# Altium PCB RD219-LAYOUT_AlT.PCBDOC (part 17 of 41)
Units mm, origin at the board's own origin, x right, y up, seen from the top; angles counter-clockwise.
Board outline 209.75 x 159.97 mm, 2 copper layers (TOP, BOTTOM), stack 0 mm thick; 398 components, 199 nets, 1469 pads, 0 vias.
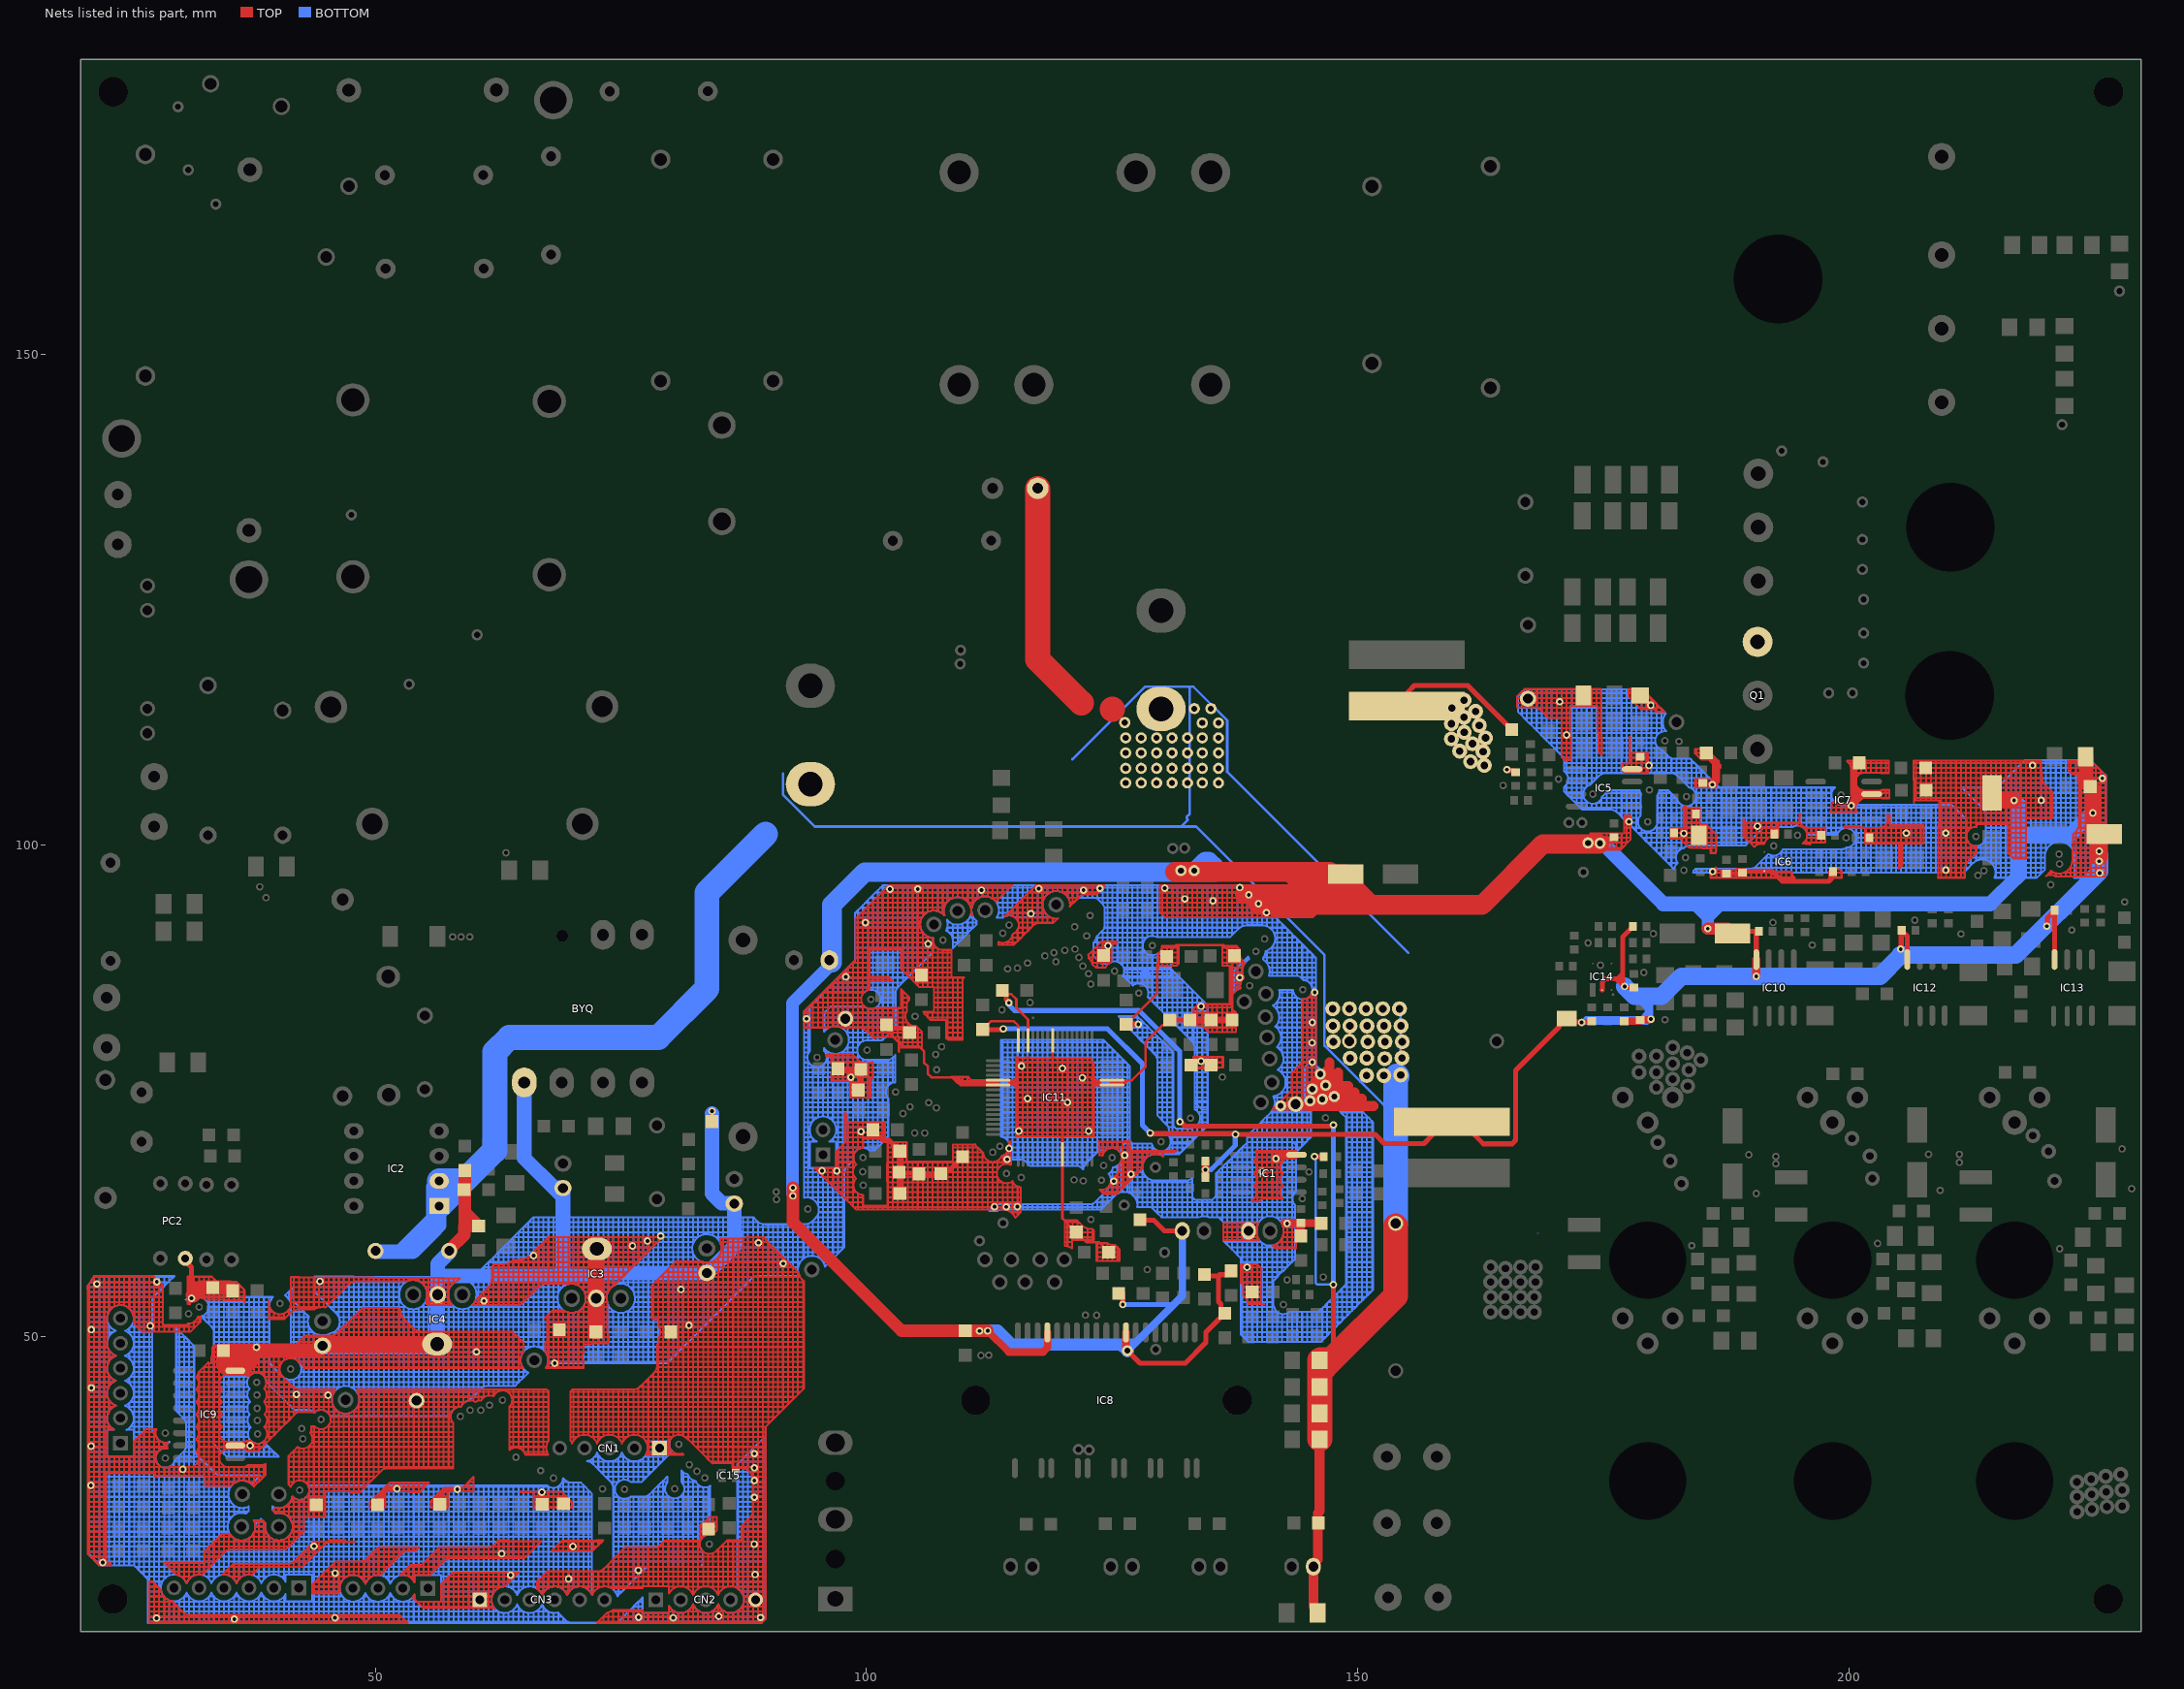
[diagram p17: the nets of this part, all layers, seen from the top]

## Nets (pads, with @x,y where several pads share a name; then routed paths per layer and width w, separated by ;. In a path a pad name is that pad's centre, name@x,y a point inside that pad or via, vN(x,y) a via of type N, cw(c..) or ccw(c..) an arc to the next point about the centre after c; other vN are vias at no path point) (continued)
GND: (continued)
  TOP w0.203: 201.737,101.775 202.245,101.775 ; 201.737,104.849 202.245,104.849 ; 201.737,104.849 201.737,105.217 IC7.3@201.737,105.344 ; IC7.3@201.737,105.344 IC7.3@202.245,105.344 ; IC7.3@201.737,105.344 201.737,105.585 ; 201.737,105.585 202.245,105.585 ; 201.737,107.389 202.245,107.389 ; 201.737,107.389 201.737,107.884 ; 201.737,107.884 202.245,107.884 ; 201.737,107.884 201.737,108.392 ; 201.737,108.392 202.245,108.392 ; 201.737,108.392 201.737,108.631 ; 201.737,108.631 202.245,108.631 ; 202.245,100.173 202.245,100.264 ; 202.245,100.264 202.753,100.264 ; 202.245,100.264 C17.1@202.245,100.772 ; C17.1@202.245,100.772 202.753,100.772 ; C17.1@202.245,100.772 202.245,101.28 ; 202.245,101.28 202.753,101.28 ; 202.245,101.28 202.245,101.775 ; 202.245,101.775 202.753,101.775 ; 202.245,104.849 202.753,104.849 ; 202.245,104.849 202.245,105.217 IC7.3@202.245,105.344 ; IC7.3@202.245,105.344 202.245,105.585 ; IC7.3@202.245,105.344 IC7.3@202.753,105.344 ; 202.245,105.585 202.753,105.585 ; 202.245,107.389 202.245,107.884 ; 202.245,107.389 202.753,107.389 ; 202.245,107.884 202.245,108.392 ; 202.245,107.884 202.753,107.884 ; 202.245,108.392 202.245,108.631 ; 202.245,108.392 202.753,108.392 ; 202.245,108.631 202.753,108.631 ; 202.753,100.172 202.753,100.264 ; 202.753,100.172 203.261,100.172 ; 202.753,100.264 202.753,100.772 ; 202.753,100.264 203.261,100.264 ; 202.753,100.772 203.261,100.772 ; 202.753,100.772 202.753,101.28 ; 202.753,101.28 203.261,101.28 ; 202.753,101.28 202.753,101.775 ; 202.753,101.775 203.051,101.775 ccw(c203.051,102.677) 203.201,101.788 ; 202.753,104.849 203.051,104.849 cw(c203.051,103.947) 203.201,104.836 ; 202.753,104.849 202.753,105.217 IC7.3@202.753,105.344 ; IC7.3@202.753,105.344 IC7.3@203.261,105.344 ; IC7.3@202.753,105.344 202.753,105.585 ; 202.753,105.585 203.051,105.585 ccw(c203.051,106.487) 203.261,105.61 ; 202.753,107.389 202.753,107.884 ; 202.753,107.389 203.051,107.389 cw(c203.051,106.487) 203.201,107.376 ; 202.753,107.884 203.261,107.884 ; 202.753,107.884 202.753,108.392 ; 202.753,108.392 203.261,108.392 ; 202.753,108.392 202.753,108.631 ; 202.753,108.631 203.261,108.631 ; 203.201,101.788 ccw(c203.051,102.677) 203.261,101.8 ; 203.201,101.788 203.261,101.788 ; 203.201,104.836 cw(c203.051,103.947) 203.261,104.824 ; 203.201,104.836 203.261,104.836 ; 203.201,107.376 cw(c203.051,106.487) 203.261,107.364 ; 203.201,107.376 203.261,107.376 ; 203.261,100.172 203.261,100.264 ; 203.261,100.172 203.769,100.172 ; 203.261,100.264 203.261,100.772 ; 203.261,100.264 203.769,100.264 ; 203.261,100.772 203.261,101.28 ; 203.261,100.772 203.769,100.772 ; 203.261,101.28 203.261,101.788 ; 203.261,101.28 203.769,101.28 ; 203.261,101.788 203.769,101.788 ; 203.261,101.788 203.261,101.8 ; 203.261,101.8 ccw(c203.051,102.677) 203.769,102.132 ; 203.261,104.824 203.261,104.836 ; 203.261,104.836 203.769,104.836 ; 203.261,104.836 IC7.3@203.261,105.344 ; IC7.3@203.261,105.344 203.769,105.344 ; IC7.3@203.261,105.344 203.261,105.61 ; 203.261,107.364 203.261,107.376 ; 203.261,107.376 203.769,107.376 ; 203.261,107.376 203.261,107.884 ; 203.261,107.884 203.769,107.884 ; 203.261,107.884 203.261,108.392 ; 203.261,108.392 203.769,108.392 ; 203.261,108.392 203.261,108.631 ; 203.261,108.631 203.769,108.631 ; 203.769,100.172 204.277,100.172 ; 203.769,100.172 203.769,100.264 ; 203.769,100.264 204.277,100.264 ; 203.769,100.264 203.769,100.772 ; 203.769,100.772 204.277,100.772 ; 203.769,100.772 203.769,101.28 ; 203.769,101.28 204.277,101.28 ; 203.769,101.28 203.769,101.788 ; 203.769,101.788 204.277,101.788 ; 203.769,101.788 203.769,102.132 ; 203.769,102.132 ccw(c203.051,102.677) 203.771,102.134 ccw(c203.051,102.677) 203.868,102.296 ; 203.769,104.799 203.769,104.836 ; 203.769,104.799 204.092,104.799 204.092,104.836 ; 203.769,104.836 203.769,105.344 ; 203.769,104.836 204.092,104.836 ; 203.769,105.344 203.769,105.635 ; 203.769,105.344 204.092,105.344 ; 203.769,105.635 204.092,105.635 204.092,105.344 ; 203.769,107.339 203.769,107.376 ; 203.769,107.339 204.041,107.339 204.041,107.376 ; 203.769,107.376 203.769,107.884 ; 203.769,107.376 204.041,107.376 ; 203.769,107.884 203.769,108.392 ; 203.769,107.884 204.041,107.884 ; 203.769,108.392 203.769,108.631 ; 203.769,108.392 204.041,108.392 ; 203.769,108.631 204.041,108.631 204.041,108.392 ; 203.85,103.095 cw(c203.051,102.677) 203.944,102.804 ; 203.85,103.095 204.168,103.095 204.168,102.804 ; 203.868,102.296 ccw(c203.051,102.677) 203.953,102.677 ccw(c203.051,102.677) 203.944,102.804 ; 203.868,102.296 204.168,102.296 ; 203.944,102.804 204.168,102.804 ; 204.041,107.376 204.041,107.884 ; 204.041,107.884 204.041,108.392 ; 204.092,104.836 204.092,105.344 ; 204.168,102.296 204.168,102.804 ; 204.168,102.296 204.168,102.06 204.277,102.06 ; 204.277,100.172 204.277,100.264 ; 204.277,100.172 204.785,100.172 ; 204.277,100.264 204.277,100.772 ; 204.277,100.264 204.785,100.264 ; 204.277,100.772 204.277,101.28 ; 204.277,100.772 204.785,100.772 ; 204.277,101.28 204.277,101.788 ; 204.277,101.28 204.785,101.28 ; 204.277,101.788 204.785,101.788 ; 204.277,101.788 204.277,102.06 ; 204.277,102.06 204.785,102.06 ; 204.785,100.172 204.785,100.264 ; 204.785,100.172 205.078,100.172 205.078,99.756 ; 204.785,100.264 204.785,100.772 ; 204.785,100.264 205.293,100.264 ; 204.785,100.772 204.785,101.28 ; 204.785,100.772 205.293,100.772 ; 204.785,101.28 204.785,101.788 ; 204.785,101.28 205.293,101.28 ; 204.785,101.788 204.785,102.06 ; 204.785,101.788 205.293,101.788 ; 204.785,102.06 205.293,102.06 ; 205.078,97.724 205.078,98.232 ; 205.078,97.724 205.078,97.646 205.431,97.999 205.431,98.232 ; 205.078,98.232 205.293,98.232 ; 205.078,98.232 205.078,98.74 ; 205.078,98.74 205.293,98.74 ; 205.078,98.74 205.078,99.248 ; 205.078,99.248 205.293,99.248 ; 205.078,99.248 205.078,99.756 ; 205.078,99.756 205.293,99.756 ; 205.293,98.232 205.293,98.74 ; 205.293,98.232 205.431,98.232 ; 205.293,98.74 205.293,99.248 ; 205.293,98.74 205.431,98.74 ; 205.293,99.248 205.293,99.756 ; 205.293,99.248 205.431,99.248 ; 205.293,99.756 205.293,100.264 ; 205.293,99.756 205.431,99.756 ; 205.293,100.264 205.293,100.772 ; 205.293,100.264 205.801,100.264 ; 205.293,100.772 205.293,101.28 ; 205.293,100.772 205.801,100.772 ; 205.293,101.28 205.293,101.788 ; 205.293,101.28 pad.@205.801,101.28 ; 205.293,101.788 205.293,102.06 ; 205.293,101.788 205.801,101.788 ; 205.293,102.06 205.801,102.06 ; 205.431,98.232 205.431,98.74 ; 205.431,98.74 205.431,99.248 ; 205.431,99.248 205.431,99.756 ; 205.431,99.756 205.431,100.172 205.801,100.172 ; 205.801,100.172 205.801,100.264 ; 205.801,100.172 206.309,100.172 ; 205.801,100.264 205.801,100.772 ; 205.801,100.264 206.309,100.264 ; 205.801,100.772 206.309,100.772 ; 205.801,100.772 pad.@205.801,101.28 ; pad.@205.801,101.28 205.801,101.788 ; pad.@205.801,101.28 206.309,101.28 ; 205.801,101.788 205.801,102.06 ; 205.801,101.788 206.309,101.788 ; 205.801,102.06 206.309,102.06 ; 206.309,100.172 206.817,100.172 ; 206.309,100.172 206.309,100.264 ; 206.309,100.264 206.817,100.264 ; 206.309,100.264 206.309,100.772 ; 206.309,100.772 206.817,100.772 ; 206.309,100.772 206.309,101.28 ; 206.309,101.28 206.817,101.28 ; 206.309,101.28 206.309,101.788 ; 206.309,101.788 206.817,101.788 ; 206.309,101.788 206.309,102.06 ; 206.545,106.868 206.545,107.376 ; 206.545,106.868 206.817,106.868 ; 206.545,107.376 206.545,107.884 ; 206.545,107.376 206.817,107.376 ; 206.545,107.884 206.817,107.884 ; 206.545,107.884 206.545,108.392 ; 206.545,108.392 206.817,108.392 ; 206.545,108.392 206.545,108.631 206.817,108.631 ; 206.595,104.836 206.817,104.836 ; 206.595,104.836 206.595,105.344 ; 206.595,105.344 206.817,105.344 ; 206.595,105.344 206.595,105.852 ; 206.595,105.852 206.817,105.852 ; 206.595,105.852 206.595,106.36 ; 206.595,106.36 206.817,106.36 ; 206.817,100.172 206.817,100.264 ; 206.817,100.172 207.325,100.172 ; 206.817,100.264 206.817,100.772 ; 206.817,100.264 207.325,100.264 ; 206.817,100.772 206.817,101.28 ; 206.817,100.772 207.325,100.772 ; 206.817,101.28 206.817,101.788 ; 206.817,101.28 207.325,101.28 ; 206.817,101.788 206.817,102.06 ; 206.817,101.788 207.325,101.788 ; 206.817,102.06 207.325,102.06 ; 206.817,104.564 207.325,104.564 ; 206.817,104.564 206.817,104.836 ; 206.817,104.836 206.817,105.344 ; 206.817,104.836 207.325,104.836 ; 206.817,105.344 206.817,105.852 ; 206.817,105.344 C20.1@207.325,105.344 ; 206.817,105.852 206.817,106.36 ; 206.817,105.852 C20.1@207.325,105.852 ; 206.817,106.36 206.817,106.868 ; 206.817,106.36 207.325,106.36 ; 206.817,106.868 206.817,107.376 ; 206.817,106.868 207.325,106.868 ; 206.817,107.376 206.817,107.884 ; 206.817,107.376 R42.1@207.325,107.376 ; 206.817,107.884 206.817,108.392 ; 206.817,107.884 R42.1@207.325,107.884 ; 206.817,108.392 206.817,108.631 ; 206.817,108.392 R42.1@207.325,108.392 ; 206.817,108.631 207.325,108.631 ; 207.325,100.172 207.325,100.264 ; 207.325,100.172 207.612,100.172 207.612,100.264 ; 207.325,100.264 207.325,100.772 ; 207.325,100.264 207.612,100.264 ; 207.325,100.772 207.325,101.28 ; 207.325,100.772 207.612,100.772 ; 207.325,101.28 207.325,101.788 ; 207.325,101.28 207.612,101.28 ; 207.325,101.788 207.325,102.06 ; 207.325,101.788 207.612,101.788 ; 207.325,102.06 207.612,102.06 207.612,101.788 ; 207.325,104.564 207.325,104.836 ; 207.325,104.564 207.833,104.564 ; 207.325,104.836 C20.1@207.325,105.344 ; 207.325,104.836 207.833,104.836 ; C20.1@207.325,105.344 C20.1@207.833,105.344 ; C20.1@207.325,105.344 C20.1@207.325,105.852 ; C20.1@207.325,105.852 207.325,106.36 ; C20.1@207.325,105.852 C20.1@207.833,105.852 ; 207.325,106.36 207.325,106.868 ; 207.325,106.36 207.833,106.36 ; 207.325,106.868 R42.1@207.325,107.376 ; 207.325,106.868 207.833,106.868 ; R42.1@207.325,107.376 R42.1@207.833,107.376 ; R42.1@207.325,107.376 R42.1@207.325,107.884 ; R42.1@207.325,107.884 R42.1@207.782,107.884 R42.1@207.833,107.884 ; R42.1@207.325,107.884 R42.1@207.325,108.392 ; R42.1@207.325,108.392 207.325,108.631 ; R42.1@207.325,108.392 R42.1@207.833,108.392 ; 207.325,108.631 207.833,108.631 ; 207.612,100.264 207.612,100.772 ; 207.612,100.772 207.612,101.28 ; 207.612,101.28 207.612,101.788 ; 207.833,104.564 207.833,104.836 ; 207.833,104.564 208.341,104.564 ; 207.833,104.836 C20.1@207.833,105.344 ; 207.833,104.836 208.341,104.836 ; C20.1@207.833,105.344 C20.1@207.833,105.852 ; C20.1@207.833,105.344 C20.1@208.341,105.344 ; C20.1@207.833,105.852 207.833,106.36 ; C20.1@207.833,105.852 C20.1@208.341,105.852 ; 207.833,106.36 207.833,106.868 ; 207.833,106.36 208.341,106.36 ; 207.833,106.868 R42.1@207.833,107.376 ; 207.833,106.868 208.341,106.868 ; R42.1@207.833,107.376 R42.1@208.341,107.376 ; R42.1@207.833,107.376 R42.1@207.833,107.884 ; R42.1@207.833,107.884 R42.1@208.341,107.884 ; R42.1@207.833,107.884 R42.1@207.833,108.392 ; R42.1@207.833,108.392 207.833,108.631 ; R42.1@207.833,108.392 R42.1@208.341,108.392 ; 207.833,108.631 208.341,108.631 ; 208.341,104.564 208.341,104.836 ; 208.341,104.564 208.849,104.564 ; 208.341,104.836 C20.1@208.341,105.344 ; 208.341,104.836 208.849,104.836 ; C20.1@208.341,105.344 208.849,105.344 ; C20.1@208.341,105.344 C20.1@208.341,105.852 ; C20.1@208.341,105.852 208.341,106.36 ; C20.1@208.341,105.852 208.849,105.852 ; 208.341,106.36 208.341,106.868 ; 208.341,106.36 208.849,106.36 ; 208.341,106.868 R42.1@208.341,107.376 ; 208.341,106.868 208.849,106.868 ; R42.1@208.341,107.376 208.849,107.376 ; R42.1@208.341,107.376 R42.1@208.341,107.884 ; R42.1@208.341,107.884 208.849,107.884 ; R42.1@208.341,107.884 R42.1@208.341,108.392 ; R42.1@208.341,108.392 208.341,108.631 ; R42.1@208.341,108.392 208.849,108.392 ; 208.341,108.631 208.849,108.631 ; 208.849,104.564 208.849,104.836 ; 208.849,104.564 209.161,104.564 209.161,104.328 ; 208.849,104.836 208.849,105.344 ; 208.849,104.836 209.357,104.836 ; 208.849,105.344 208.849,105.852 ; 208.849,105.344 209.357,105.344 ; 208.849,105.852 208.849,106.36 ; 208.849,105.852 209.357,105.852 ; 208.849,106.36 208.849,106.868 ; 208.849,106.36 209.357,106.36 ; 208.849,106.868 208.849,107.376 ; 208.849,106.868 209.357,106.868 ; 208.849,107.376 208.849,107.884 ; 208.849,107.376 209.357,107.376 ; 208.849,107.884 208.849,108.392 ; 208.849,107.884 209.357,107.884 ; 208.849,108.392 208.849,108.631 ; 208.849,108.392 209.357,108.392 ; 208.849,108.631 209.357,108.631 ; 209.059,96.708 ccw(c208.341,96.835) 209.07,96.835 ; 209.059,96.708 ccw(c208.341,96.835) 209.07,96.835 ; 209.058,96.708 209.357,96.708 ; 209.058,96.708 209.357,96.708 ; 209.07,96.835 209.07,97.216 ; 209.07,97.216 209.357,97.216 ; 209.07,97.216 209.07,97.724 ; 209.07,97.724 209.357,97.724 ; 209.07,97.724 209.07,98.232 ; 209.07,98.232 209.357,98.232 ; 209.07,98.232 209.07,98.74 ; 209.07,98.74 209.07,99.248 ; 209.07,98.74 209.357,98.74 ; 209.07,99.248 209.07,99.756 ; 209.07,99.248 209.357,99.248 ; 209.07,99.756 209.07,100.264 ; 209.07,99.756 209.357,99.756 ; 209.07,100.264 209.357,100.264 ; 209.07,100.264 209.07,100.772 ; 209.07,100.772 209.357,100.772 ; 209.07,100.772 209.07,101.28 ; 209.07,101.28 209.357,101.28 ; 209.07,101.28 209.07,101.788 ; 209.07,101.788 209.357,101.788 ; 209.07,101.788 209.07,102.06 209.161,102.06 209.161,102.296 ; 209.161,102.296 209.357,102.296 ; 209.161,102.296 209.161,102.804 ; 209.161,102.804 209.357,102.804 ; 209.161,102.804 209.161,103.312 ; 209.161,103.312 209.357,103.312 ; 209.161,103.312 209.161,103.82 ; 209.161,103.82 209.357,103.82 ; 209.161,103.82 209.161,104.328 ; 209.161,104.328 209.357,104.328 ; 209.357,96.708 209.357,97.216 ; 209.357,96.708 209.865,96.708 ; 209.357,96.708 209.865,96.708 ; 209.357,97.216 209.357,97.724 ; 209.357,97.216 pad.@209.865,97.216 ; 209.357,97.724 209.357,98.232 ; 209.357,97.724 pad.@209.865,97.724 ; 209.357,98.232 209.357,98.74 ; 209.357,98.232 209.865,98.232 ; 209.357,98.74 209.357,99.248 ; 209.357,98.74 209.865,98.74 ; 209.357,99.248 209.357,99.756 ; 209.357,99.248 209.865,99.248 ; 209.357,99.756 209.357,100.264 ; 209.357,99.756 209.865,99.756 ; 209.357,100.264 209.357,100.772 ; 209.357,100.264 209.865,100.264 ; 209.357,100.772 209.357,101.28 ; 209.357,100.772 209.865,100.772 ; 209.357,101.28 209.357,101.788 ; 209.357,101.28 pad.@209.865,101.28 ; 209.357,101.788 209.357,102.296 ; 209.357,101.788 209.865,101.788 ; 209.357,102.296 209.357,102.804 ; 209.357,102.296 209.865,102.296 ; 209.357,102.804 209.357,103.312 ; 209.357,102.804 209.865,102.804 ; 209.357,103.312 209.357,103.82 ; 209.357,103.312 209.865,103.312 ; 209.357,103.82 209.357,104.328 ; 209.357,103.82 209.865,103.82 ; 209.357,104.328 209.357,104.836 ; 209.357,104.328 209.865,104.328 ; 209.357,104.836 209.357,105.344 ; 209.357,104.836 209.865,104.836 ; 209.357,105.344 209.357,105.852 ; 209.357,105.344 209.865,105.344 ; 209.357,105.852 209.357,106.36 ; 209.357,105.852 209.865,105.852 ; 209.357,106.36 209.357,106.868 ; 209.357,106.36 209.865,106.36 ; 209.357,106.868 209.357,107.376 ; 209.357,106.868 209.865,106.868 ; 209.357,107.376 209.357,107.884 ; 209.357,107.376 209.865,107.376 ; 209.357,107.884 209.357,108.392 ; 209.357,107.884 209.865,107.884 ; 209.357,108.392 209.357,108.631 ; 209.357,108.392 209.865,108.392 ; 209.357,108.631 209.865,108.631 ; 209.865,96.708 pad.@209.865,97.216 ; 209.865,96.708 210.373,96.708 ; 209.865,96.708 210.373,96.708 ; pad.@209.865,97.216 210.373,97.216 ; pad.@209.865,97.216 pad.@209.865,97.724 ; pad.@209.865,97.724 209.865,98.232 ; pad.@209.865,97.724 210.373,97.724 ; 209.865,98.232 209.865,98.74 ; 209.865,98.232 210.373,98.232 ; 209.865,98.74 209.865,99.248 ; 209.865,98.74 210.373,98.74 ; 209.865,99.248 209.865,99.756 ; 209.865,99.248 210.373,99.248 ; 209.865,99.756 209.865,100.264 ; 209.865,99.756 210.373,99.756 ; 209.865,100.264 209.865,100.772 ; 209.865,100.264 210.373,100.264 ; 209.865,100.772 210.373,100.772 ; 209.865,100.772 pad.@209.865,101.28 ; pad.@209.865,101.28 209.865,101.788 ; pad.@209.865,101.28 210.373,101.28 ; 209.865,101.788 209.865,102.296 ; 209.865,101.788 210.373,101.788 ; 209.865,102.296 209.865,102.804 ; 209.865,102.296 210.373,102.296 ; 209.865,102.804 209.865,103.312 ; 209.865,102.804 210.373,102.804 ; 209.865,103.312 209.865,103.82 ; 209.865,103.312 210.373,103.312 ; 209.865,103.82 209.865,104.328 ; 209.865,103.82 210.373,103.82 ; 209.865,104.328 209.865,104.836 ; 209.865,104.328 210.373,104.328 ; 209.865,104.836 209.865,105.344 ; 209.865,104.836 210.373,104.836 ; 209.865,105.344 209.865,105.852 ; 209.865,105.344 210.373,105.344 ; 209.865,105.852 209.865,106.36 ; 209.865,105.852 210.373,105.852 ; 209.865,106.36 209.865,106.868 ; 209.865,106.36 210.373,106.36 ; 209.865,106.868 209.865,107.376 ; 209.865,106.868 210.373,106.868 ; 209.865,107.376 209.865,107.884 ; 209.865,107.376 210.373,107.376 ; 209.865,107.884 209.865,108.392 ; 209.865,107.884 210.373,107.884 ; 209.865,108.392 209.865,108.631 ; 209.865,108.392 210.373,108.392 ; 209.865,108.631 210.373,108.631 ; 210.373,96.708 210.373,97.216 ; 210.373,96.708 210.881,96.708 ; 210.373,96.708 210.881,96.708 ; 210.373,97.216 210.373,97.724 ; 210.373,97.216 210.881,97.216 ; 210.373,97.724 210.373,98.232 ; 210.373,97.724 210.881,97.724 ; 210.373,98.232 210.373,98.74 ; 210.373,98.232 210.881,98.232 ; 210.373,98.74 210.373,99.248 ; 210.373,98.74 210.881,98.74 ; 210.373,99.248 210.373,99.756 ; 210.373,99.248 210.881,99.248 ; 210.373,99.756 210.373,100.264 ; 210.373,99.756 210.881,99.756 ; 210.373,100.264 210.373,100.772 ; 210.373,100.264 210.881,100.264 ; 210.373,100.772 210.373,101.28 ; 210.373,100.772 210.881,100.772 ; 210.373,101.28 210.373,101.788 ; 210.373,101.28 210.881,101.28 ; 210.373,101.788 210.373,102.296 ; 210.373,101.788 210.881,101.788 ; 210.373,102.296 210.373,102.804 ; 210.373,102.296 210.881,102.296 ; 210.373,102.804 210.373,103.312 ; 210.373,102.804 210.881,102.804 ; 210.373,103.312 210.373,103.82 ; 210.373,103.312 210.881,103.312 ; 210.373,103.82 210.373,104.328 ; 210.373,103.82 210.881,103.82 ; 210.373,104.328 210.373,104.836 ; 210.373,104.328 210.881,104.328 ; 210.373,104.836 210.373,105.344 ; 210.373,104.836 210.881,104.836 ; 210.373,105.344 210.373,105.852 ; 210.373,105.344 210.881,105.344 ; 210.373,105.852 210.373,106.36 ; 210.373,105.852 210.881,105.852 ; 210.373,106.36 210.373,106.868 ; 210.373,106.36 210.881,106.36 ; 210.373,106.868 210.373,107.376 ; 210.373,106.868 210.881,106.868 ; 210.373,107.376 210.373,107.884 ; 210.373,107.376 210.881,107.376 ; 210.373,107.884 210.373,108.392 ; 210.373,107.884 210.881,107.884 ; 210.373,108.392 210.373,108.631 ; 210.373,108.392 210.881,108.392 ; 210.373,108.631 210.881,108.631 ; 210.881,96.708 210.881,97.216 ; 210.881,96.708 211.389,96.708 ; 210.881,96.708 211.389,96.708 ; 210.881,97.216 210.881,97.724 ; 210.881,97.216 211.389,97.216 ; 210.881,97.724 210.881,98.232 ; 210.881,97.724 211.389,97.724 ; 210.881,98.232 210.881,98.74 ; 210.881,98.232 211.389,98.232 ; 210.881,98.74 210.881,99.248 ; 210.881,98.74 211.389,98.74 ; 210.881,99.248 210.881,99.756 ; 210.881,99.248 211.389,99.248 ; 210.881,99.756 210.881,100.264 ; 210.881,99.756 211.389,99.756 ; 210.881,100.264 210.881,100.772 ; 210.881,100.264 211.389,100.264 ; 210.881,100.772 210.881,101.28 ; 210.881,100.772 211.389,100.772 ; 210.881,101.28 210.881,101.788 ; 210.881,101.28 211.389,101.28 ; 210.881,101.788 210.881,102.296 ; 210.881,101.788 211.389,101.788 ; 210.881,102.296 210.881,102.804 ; 210.881,102.296 211.389,102.296 ; 210.881,102.804 210.881,103.312 ; 210.881,102.804 211.389,102.804 ; 210.881,103.312 210.881,103.82 ; 210.881,103.312 211.389,103.312 ; 210.881,103.82 210.881,104.328 ; 210.881,103.82 211.389,103.82 ; 210.881,104.328 210.881,104.836 ; 210.881,104.328 211.389,104.328 ; 210.881,104.836 210.881,105.344 ; 210.881,104.836 211.389,104.836 ; 210.881,105.344 210.881,105.852 ; 210.881,105.344 211.389,105.344 ; 210.881,105.852 210.881,106.36 ; 210.881,105.852 211.389,105.852 ; 210.881,106.36 210.881,106.868 ; 210.881,106.36 211.389,106.36 ; 210.881,106.868 210.881,107.376 ; 210.881,106.868 211.389,106.868 ; 210.881,107.376 210.881,107.884 ; 210.881,107.376 211.389,107.376 ; 210.881,107.884 210.881,108.392 ; 210.881,107.884 211.389,107.884 ; 210.881,108.392 210.881,108.631 ; 210.881,108.392 211.389,108.392 ; 210.881,108.631 211.389,108.631 ; 211.389,96.708 211.389,97.216 ; 211.389,96.708 211.792,96.708 211.389,96.708 ; 211.389,97.216 211.389,97.724 ; 211.389,97.216 211.771,97.216 ; 211.389,97.724 211.389,98.232 ; 211.389,97.724 211.789,97.724 ; 211.389,98.232 211.897,98.232 ; 211.389,98.232 211.389,98.74 ; 211.389,98.74 211.389,99.248 ; 211.389,98.74 211.897,98.74 ; 211.389,99.248 211.389,99.756 ; 211.389,99.248 211.897,99.248 ; 211.389,99.756 211.389,100.264 ; 211.389,99.756 211.897,99.756 ; 211.389,100.264 211.389,100.772 ; 211.389,100.264 211.897,100.264 ; 211.389,100.772 211.897,100.772 ; 211.389,100.772 211.389,101.28 ; 211.389,101.28 211.389,101.788 ; 211.389,101.28 211.897,101.28 ; 211.389,101.788 211.389,102.296 ; 211.389,101.788 211.897,101.788 ; 211.389,102.296 211.389,102.804 ; 211.389,102.296 211.897,102.296 ; 211.389,102.804 211.389,103.312 ; 211.389,102.804 211.897,102.804 ; 211.389,103.312 211.389,103.82 ; 211.389,103.312 211.897,103.312 ; 211.389,103.82 211.389,104.328 ; 211.389,103.82 211.897,103.82 ; 211.389,104.328 211.389,104.836 ; 211.389,104.328 211.897,104.328 ; 211.389,104.836 211.389,105.344 ; 211.389,104.836 211.897,104.836 ; 211.389,105.344 211.389,105.852 ; 211.389,105.344 211.897,105.344 ; 211.389,105.852 211.389,106.36 ; 211.389,105.852 211.897,105.852 ; 211.389,106.36 211.389,106.868 ; 211.389,106.36 211.897,106.36 ; 211.389,106.868 211.389,107.376 ; 211.389,106.868 211.897,106.868 ; 211.389,107.376 211.389,107.884 ; 211.389,107.376 211.897,107.376 ; 211.389,107.884 211.389,108.392 ; 211.389,107.884 211.897,107.884 ; 211.389,108.392 211.389,108.631 ; 211.389,108.392 211.897,108.392 ; 211.389,108.631 211.897,108.631 ; 211.771,96.948 ccw(c213.122,96.948) 211.791,96.713 cw(c213.122,96.948) 211.771,96.948 ; 211.771,96.948 211.771,97.216 ; 211.771,97.216 211.771,97.502 ; 211.771,97.502 cw(c213.122,97.502) 211.787,97.714 ; 211.771,97.502 cw(c213.122,97.502) 211.787,97.714 ; 211.787,97.714 cw(c213.122,97.502) 211.789,97.724 ; 211.787,97.714 cw(c213.122,97.502) 211.789,97.724 ; 211.789,97.724 cw(c213.122,97.502) 211.897,98.073 ; 211.789,97.724 cw(c213.122,97.502) 211.897,98.073 ; 211.897,98.073 cw(c213.122,97.502) 211.985,98.232 ; 211.897,98.073 cw(c213.122,97.502) 211.985,98.232 ; 211.897,98.073 211.897,98.232 ; 211.897,98.232 211.897,98.74 ; 211.897,98.232 211.985,98.232 ; 211.897,98.74 212.405,98.74 ; 211.897,98.74 211.897,99.248 ; 211.897,99.248 211.897,99.756 ; 211.897,99.248 212.405,99.248 ; 211.897,99.756 211.897,100.264 ; 211.897,99.756 212.405,99.756 ; 211.897,100.264 211.897,100.772 ; 211.897,100.264 212.168,100.264 ; 211.897,100.772 211.897,101.28 ; 211.897,100.772 211.939,100.772 ; 211.897,101.28 211.897,101.788 ; 211.897,101.28 212.005,101.28 ; 211.897,101.788 212.405,101.788 ; 211.897,101.788 211.897,102.296 ; 211.897,102.296 211.897,102.804 ; 211.897,102.296 212.405,102.296 ; 211.897,102.804 211.897,103.312 ; 211.897,102.804 212.405,102.804 ; 211.897,103.312 211.897,103.82 ; 211.897,103.312 212.405,103.312 ; 211.897,103.82 211.897,104.328 ; 211.897,103.82 212.405,103.82 ; 211.897,104.328 211.897,104.836 ; 211.897,104.328 212.405,104.328 ; 211.897,104.836 211.897,105.344 ; 211.897,104.836 212.405,104.836 ; 211.897,105.344 211.897,105.852 ; 211.897,105.344 212.405,105.344 ; 211.897,105.852 211.897,106.36 ; 211.897,105.852 212.405,105.852 ; 211.897,106.36 211.897,106.868 ; 211.897,106.36 212.405,106.36 ; 211.897,106.868 211.897,107.376 ; 211.897,106.868 212.405,106.868 ; 211.897,107.376 211.897,107.884 ; 211.897,107.376 212.405,107.376 ; 211.897,107.884 211.897,108.392 ; 211.897,107.884 212.405,107.884 ; 211.897,108.392 211.897,108.631 ; 211.897,108.392 212.405,108.392 ; 211.897,108.631 212.405,108.631 ; 211.939,100.772 ccw(c212.913,100.905) 212.168,100.264 ; 211.939,100.772 ccw(c212.913,100.905) 211.94,100.768 ccw(c212.913,100.905) 212.168,100.264 ; 211.939,100.772 cw(c212.913,100.905) 211.93,100.905 cw(c212.913,100.905) 212.002,101.273 ; 211.939,100.772 cw(c212.913,100.905) 212.002,101.273 ; 211.985,98.232 cw(c213.122,97.502) 212.167,98.458 ccw(c213.122,97.502) 211.985,98.232 ; 212.002,101.273 cw(c212.913,100.905) 212.005,101.28 ; 212.002,101.273 cw(c212.913,100.905) 212.005,101.28 ; 212.005,101.28 cw(c212.913,100.905) 212.405,101.746 ; 212.005,101.28 cw(c212.913,100.905) 212.405,101.746 ; 212.168,100.264 ccw(c212.913,100.905) 212.171,100.26 ; 212.168,100.264 ccw(c212.913,100.905) 212.171,100.26 ; 212.171,100.26 ccw(c212.913,100.905) 212.405,100.064 ; 212.171,100.26 ccw(c212.913,100.905) 212.405,100.064 ; 212.405,98.696 212.405,98.74 ; 212.405,98.696 212.449,98.74 ; 212.405,98.74 212.405,99.248 ; 212.405,98.74 212.449,98.74 ; 212.405,99.248 212.913,99.248 ; 212.405,99.248 212.405,99.756 ; 212.405,99.756 212.913,99.756 ; 212.405,99.756 212.405,100.064 ; 212.405,100.064 ccw(c212.913,100.905) 212.407,100.063 ; 212.405,100.064 ccw(c212.913,100.905) 212.407,100.063 ; 212.405,101.746 cw(c212.913,100.905) 212.482,101.788 ; 212.405,101.746 cw(c212.913,100.905) 212.482,101.788 ; 212.405,101.746 212.405,101.788 ; 212.405,101.788 212.405,102.296 ; 212.405,101.788 212.482,101.788 ; 212.405,102.296 212.405,102.804 ; 212.405,102.296 212.913,102.296 ; 212.405,102.804 212.405,103.312 ; 212.405,102.804 212.913,102.804 ; 212.405,103.312 212.405,103.82 ; 212.405,103.312 212.913,103.312 ; 212.405,103.82 212.405,104.328 ; 212.405,103.82 212.913,103.82 ; 212.405,104.328 212.405,104.836 ; 212.405,104.328 212.913,104.328 ; 212.405,104.836 212.405,105.344 ; 212.405,104.836 212.913,104.836 ; 212.405,105.344 212.405,105.852 ; 212.405,105.344 212.913,105.344 ; 212.405,105.852 212.405,106.36 ; 212.405,105.852 212.913,105.852 ; 212.405,106.36 212.405,106.868 ; 212.405,106.36 212.913,106.36 ; 212.405,106.868 212.405,107.376 ; 212.405,106.868 212.913,106.868 ; 212.405,107.376 212.405,107.884 ; 212.405,107.376 212.913,107.376 ; 212.405,107.884 212.405,108.392 ; 212.405,107.884 212.913,107.884 ; 212.405,108.392 212.405,108.631 ; 212.405,108.392 212.913,108.392 ; 212.405,108.631 212.913,108.631 ; 212.407,100.063 ccw(c212.913,100.905) 212.913,99.923 ; 212.407,100.063 ccw(c212.913,100.905) 212.913,99.923 ; 212.449,98.74 212.913,99.204 ; 212.913,99.204 212.913,99.248 ; 212.913,99.204 212.957,99.248 ; 212.913,99.248 212.913,99.756 ; 212.913,99.248 212.957,99.248 ; 212.913,99.756 212.913,99.923 ; 212.913,99.756 212.962,99.756 ; 212.913,101.888 ccw(c212.913,100.905) 212.482,101.788 cw(c212.913,100.905) 212.913,101.888 ; 212.913,101.888 212.913,102.296 ; 212.913,102.296 212.913,102.804 ; 212.913,102.296 213.421,102.296 ; 212.913,102.804 212.913,103.312 ; 212.913,102.804 213.421,102.804 ; 212.913,103.312 212.913,103.82 ; 212.913,103.312 213.421,103.312 ; 212.913,103.82 212.913,104.328 ; 212.913,103.82 213.421,103.82 ; 212.913,104.328 212.913,104.836 ; 212.913,104.328 213.421,104.328 ; 212.913,104.836 212.913,105.344 ; 212.913,104.836 213.421,104.836 ; 212.913,105.344 212.913,105.852 ; 212.913,105.344 213.421,105.344 ; 212.913,105.852 212.913,106.36 ; 212.913,105.852 213.421,105.852 ; 212.913,106.36 212.913,106.868 ; 212.913,106.36 213.421,106.36 ; 212.913,106.868 212.913,107.376 ; 212.913,106.868 213.421,106.868 ; 212.913,107.376 212.913,107.884 ; 212.913,107.376 213.421,107.376 ; 212.913,107.884 212.913,108.392 ; 212.913,107.884 213.421,107.884 ; 212.913,108.392 212.913,108.631 ; 212.913,108.392 213.421,108.392 ; 212.913,108.631 214.945,108.631 ; 212.957,99.248 212.962,99.254 212.962,99.756 ; 213.421,102.146 213.421,102.296 ; 213.421,102.146 213.929,102.146 ; 213.421,102.296 213.421,102.804 ; 213.421,102.296 213.929,102.296 ; 213.421,102.804 213.421,103.312 ; 213.421,102.804 213.929,102.804 ; 213.421,103.312 213.421,103.82 ; 213.421,103.312 213.929,103.312 ; 213.421,103.82 213.421,104.328 ; 213.421,103.82 EC15.2@213.929,103.82 ; 213.421,104.328 213.421,104.836 ; 213.421,104.328 EC15.2@213.929,104.328 ; 213.421,104.836 213.421,105.344 ; 213.421,104.836 EC15.2@213.929,104.836 ; 213.421,105.344 213.421,105.852 ; 213.421,105.344 EC15.2@213.929,105.344 ; 213.421,105.852 213.421,106.36 ; 213.421,105.852 EC15.2@213.929,105.852 ; 213.421,106.36 213.421,106.868 ; 213.421,106.36 EC15.2@213.929,106.36 ; 213.421,106.868 213.421,107.376 ; 213.421,106.868 EC15.2@213.929,106.868 ; 213.421,107.376 213.421,107.884 ; 213.421,107.376 213.929,107.376 ; 213.421,107.884 213.421,108.392 ; 213.421,107.884 213.929,107.884 ; 213.421,108.392 213.929,108.392 ; 213.929,102.146 213.929,102.296 ; 213.929,102.146 214.437,102.146 ; 213.929,102.296 213.929,102.804 ; 213.929,102.296 214.437,102.296 ; 213.929,102.804 213.929,103.312 ; 213.929,102.804 214.437,102.804 ; 213.929,103.312 EC15.2@213.929,103.82 ; 213.929,103.312 214.437,103.312 ; EC15.2@213.929,103.82 EC15.2@213.929,104.328 ; EC15.2@213.929,103.82 EC15.2@214.437,103.82 ; EC15.2@213.929,104.328 EC15.2@213.929,104.836 ; EC15.2@213.929,104.328 EC15.2@214.437,104.328 ; EC15.2@213.929,104.836 EC15.2@214.437,104.836 ; EC15.2@213.929,104.836 EC15.2@213.929,105.344 ; EC15.2@213.929,105.344 EC15.2@214.437,105.344 ; EC15.2@213.929,105.344 EC15.2@213.929,105.852 ; EC15.2@213.929,105.852 EC15.2@213.929,106.36 ; EC15.2@213.929,105.852 EC15.2@214.437,105.852 ; EC15.2@213.929,106.36 EC15.2@213.929,106.868 ; EC15.2@213.929,106.36 EC15.2@214.437,106.36 ; EC15.2@213.929,106.868 213.929,107.376 ; EC15.2@213.929,106.868 EC15.2@214.437,106.868 ; 213.929,107.376 213.929,107.884 ; 213.929,107.376 214.437,107.376 ; 213.929,107.884 213.929,108.392 ; 213.929,107.884 214.437,107.884 ; 213.929,108.392 214.437,108.392 ; 214.437,102.146 214.437,102.296 ; 214.437,102.146 214.945,102.146 ; 214.437,102.296 214.437,102.804 ; 214.437,102.296 214.945,102.296 ; 214.437,102.804 214.437,103.312 ; 214.437,102.804 214.945,102.804 ; 214.437,103.312 EC15.2@214.437,103.82 ; 214.437,103.312 214.945,103.312 ; EC15.2@214.437,103.82 EC15.2@214.437,104.328 ; EC15.2@214.437,103.82 EC15.2@214.945,103.82 ; EC15.2@214.437,104.328 EC15.2@214.437,104.836 ; EC15.2@214.437,104.328 EC15.2@214.945,104.328 ; EC15.2@214.437,104.836 214.564,104.836 EC15.2@214.945,104.836 ; EC15.2@214.437,104.836 EC15.2@214.437,105.344 ; EC15.2@214.437,105.344 EC15.2@214.564,105.344 EC15.2@214.945,105.344 ; EC15.2@214.437,105.344 EC15.2@214.437,105.852 ; EC15.2@214.437,105.852 EC15.2@214.437,106.36 ; EC15.2@214.437,105.852 EC15.2@214.945,105.852 ; EC15.2@214.437,106.36 EC15.2@214.437,106.868 ; EC15.2@214.437,106.36 EC15.2@214.945,106.36 ; EC15.2@214.437,106.868 214.437,107.376 ; EC15.2@214.437,106.868 EC15.2@214.945,106.868 ; 214.437,107.376 214.437,107.884 ; 214.437,107.376 214.945,107.376 ; 214.437,107.884 214.437,108.392 ; 214.437,107.884 214.945,107.884 ; 214.437,108.392 214.945,108.392 ; 214.945,102.146 214.945,102.296 ; 214.945,102.146 215.453,102.146 ; 214.945,102.296 214.945,102.804 ; 214.945,102.296 215.453,102.296 ; 214.945,102.804 214.945,103.312 ; 214.945,102.804 215.453,102.804 ; 214.945,103.312 EC15.2@214.945,103.82 ; 214.945,103.312 215.453,103.312 ; EC15.2@214.945,103.82 EC15.2@214.945,104.328 ; EC15.2@214.945,103.82 EC15.2@215.453,103.82 ; EC15.2@214.945,104.328 214.945,104.568 EC15.2@214.945,104.836 ; EC15.2@214.945,104.328 EC15.2@215.453,104.328 ; EC15.2@214.945,104.836 EC15.2@215.453,104.836 ; EC15.2@214.945,104.836 EC15.2@214.945,105.344 ; EC15.2@214.945,105.344 EC15.2@215.453,105.344 ; EC15.2@214.945,105.344 EC15.2@214.945,105.852 ; EC15.2@214.945,105.852 EC15.2@214.945,106.36 ; EC15.2@214.945,105.852 EC15.2@215.453,105.852 ; EC15.2@214.945,106.36 EC15.2@214.945,106.868 ; EC15.2@214.945,106.36 EC15.2@215.453,106.36 ; EC15.2@214.945,106.868 214.945,107.376 ; EC15.2@214.945,106.868 EC15.2@215.453,106.868 ; 214.945,107.376 214.945,107.884 ; 214.945,107.376 215.453,107.376 ; 214.945,107.884 214.945,108.392 ; 214.945,107.884 215.453,107.884 ; 214.945,108.392 214.945,108.631 ; 214.945,108.392 215.453,108.392 ; 214.945,108.631 215.453,108.631 ; 215.453,102.146 215.453,102.296 ; 215.453,102.146 215.961,102.146 ; 215.453,102.296 215.453,102.804 ; 215.453,102.296 215.961,102.296 ; 215.453,102.804 215.453,103.312 ; 215.453,102.804 215.961,102.804 ; 215.453,103.312 EC15.2@215.453,103.82 ; 215.453,103.312 215.961,103.312 ; EC15.2@215.453,103.82 EC15.2@215.453,104.328 ; EC15.2@215.453,103.82 215.961,103.82 ; EC15.2@215.453,104.328 215.453,104.568 EC15.2@215.453,104.836 ; EC15.2@215.453,104.328 215.961,104.328 ; EC15.2@215.453,104.836 215.961,104.836 ; EC15.2@215.453,104.836 EC15.2@215.453,105.344 ; EC15.2@215.453,105.344 215.961,105.344 ; EC15.2@215.453,105.344 EC15.2@215.453,105.852 ; EC15.2@215.453,105.852 EC15.2@215.453,106.36 ; EC15.2@215.453,105.852 215.961,105.852 ; EC15.2@215.453,106.36 EC15.2@215.453,106.868 ; EC15.2@215.453,106.36 215.961,106.36 ; EC15.2@215.453,106.868 215.453,107.376 ; EC15.2@215.453,106.868 215.961,106.868 ; 215.453,107.376 215.453,107.884 ; 215.453,107.376 215.961,107.376 ; 215.453,107.884 215.453,108.392 ; 215.453,107.884 215.961,107.884 ; 215.453,108.392 215.453,108.631 ; 215.453,108.392 215.961,108.392 ; 215.453,108.631 215.961,108.631 ; 215.961,102.146 215.961,102.296 ; 215.961,102.146 216.166,102.146 216.166,101.788 ; 215.961,102.296 215.961,102.804 ; 215.961,102.296 216.469,102.296 ; 215.961,102.804 215.961,103.312 ; 215.961,102.804 216.469,102.804 ; 215.961,103.312 215.961,103.82 ; 215.961,103.312 216.469,103.312 ; 215.961,103.82 215.961,104.328 ; 215.961,103.82 216.469,103.82 ; 215.961,104.328 215.961,104.568 215.961,104.836 ; 215.961,104.328 216.469,104.328 ; 215.961,104.836 215.961,105.344 ; 215.961,104.836 216.469,104.836 ; 215.961,105.344 215.961,105.852 ; 215.961,105.344 216.469,105.344 ; 215.961,105.852 215.961,106.36 ; 215.961,105.852 216.469,105.852 ; 215.961,106.36 215.961,106.868 ; 215.961,106.36 216.469,106.36 ; 215.961,106.868 215.961,107.376 ; 215.961,106.868 216.469,106.868 ; 215.961,107.376 215.961,107.884 ; 215.961,107.376 216.469,107.376 ; 215.961,107.884 215.961,108.392 ; 215.961,107.884 216.469,107.884 ; 215.961,108.392 215.961,108.631 ; 215.961,108.392 216.469,108.392 ; 215.961,108.631 216.469,108.631 ; 216.166,99.756 216.166,99.254 216.171,99.248 ; 216.166,99.756 216.469,99.756 ; 216.166,99.756 216.166,100.264 ; 216.166,100.264 216.166,100.772 ; 216.166,100.264 216.469,100.264 ; 216.166,100.772 216.166,101.28 ; 216.166,100.772 216.469,100.772 ; 216.166,101.28 216.469,101.28 ; 216.166,101.28 216.166,101.788 ; 216.166,101.788 216.469,101.788 ; 216.171,99.248 216.469,98.95 ; 216.171,99.248 216.469,99.248 ; 216.469,98.95 216.679,98.74 ; 216.469,98.95 216.469,99.248 ; 216.469,99.248 216.977,99.248 ; 216.469,99.248 216.469,99.756 ; 216.469,99.756 216.469,100.264 ; 216.469,99.756 216.977,99.756 ; 216.469,100.264 216.469,100.772 ; 216.469,100.264 216.977,100.264 ; 216.469,100.772 216.977,100.772 ; 216.469,100.772 216.469,101.28 ; 216.469,101.28 216.469,101.788 ; 216.469,101.28 216.977,101.28 ; 216.469,101.788 216.469,102.296 ; 216.469,101.788 216.977,101.788 ; 216.469,102.296 216.469,102.804 ; 216.469,102.296 216.977,102.296 ; 216.469,102.804 216.469,103.312 ; 216.469,102.804 216.977,102.804 ; 216.469,103.312 216.469,103.82 ; 216.469,103.312 216.977,103.312 ; 216.469,103.82 216.469,104.328 ; 216.469,103.82 216.977,103.82 ; 216.469,104.328 pad.@216.977,104.328 ; 216.469,104.328 216.469,104.568 216.469,104.836 ; 216.469,104.836 216.469,105.344 ; 216.469,104.836 pad.@216.977,104.836 ; 216.469,105.344 216.469,105.852 ; 216.469,105.344 216.977,105.344 ; 216.469,105.852 216.469,106.36 ; 216.469,105.852 216.977,105.852 ; 216.469,106.36 216.469,106.868 ; 216.469,106.36 216.977,106.36 ; 216.469,106.868 216.469,107.376 ; 216.469,106.868 216.977,106.868 ; 216.469,107.376 216.469,107.884 ; 216.469,107.376 216.977,107.376 ; 216.469,107.884 216.469,108.392 ; 216.469,107.884 216.977,107.884 ; 216.469,108.392 216.469,108.631 ; 216.469,108.392 216.977,108.392 ; 216.469,108.631 216.977,108.631 ; 216.679,98.74 216.775,98.645 216.977,98.645 ; 216.679,98.74 216.977,98.74 ; 216.977,98.645 216.977,98.74 ; 216.977,98.645 217.485,98.645 ; 216.977,98.74 216.977,99.248 ; 216.977,98.74 217.485,98.74 ; 216.977,99.248 217.485,99.248 ; 216.977,99.248 216.977,99.756 ; 216.977,99.756 216.977,100.264 ; 216.977,99.756 217.485,99.756 ; 216.977,100.264 216.977,100.772 ; 216.977,100.264 217.485,100.264 ; 216.977,100.772 217.485,100.772 ; 216.977,100.772 216.977,101.28 ; 216.977,101.28 216.977,101.788 ; 216.977,101.28 217.485,101.28 ; 216.977,101.788 216.977,102.296 ; 216.977,101.788 217.485,101.788 ; 216.977,102.296 216.977,102.804 ; 216.977,102.296 217.485,102.296 ; 216.977,102.804 216.977,103.312 ; 216.977,102.804 217.485,102.804 ; 216.977,103.312 216.977,103.82 ; 216.977,103.312 217.485,103.312 ; 216.977,103.82 pad.@216.977,104.328 ; 216.977,103.82 217.485,103.82 ; pad.@216.977,104.328 217.485,104.328 ; pad.@216.977,104.328 pad.@216.977,104.836 ; pad.@216.977,104.836 216.977,105.344 ; pad.@216.977,104.836 217.485,104.836 ; 216.977,105.344 216.977,105.852 ; 216.977,105.344 217.485,105.344 ; 216.977,105.852 216.977,106.36 ; 216.977,105.852 217.485,105.852 ; 216.977,106.36 216.977,106.868 ; 216.977,106.36 217.485,106.36 ; 216.977,106.868 216.977,107.376 ; 216.977,106.868 217.485,106.868 ; 216.977,107.376 216.977,107.884 ; 216.977,107.376 217.485,107.376 ; 216.977,107.884 216.977,108.392 ; 216.977,107.884 217.485,107.884 ; 216.977,108.392 216.977,108.631 ; 216.977,108.392 217.485,108.392 ; 216.977,108.631 217.485,108.631 ; 217.485,98.645 217.993,98.645 ; 217.485,98.645 217.485,98.74 ; 217.485,98.74 217.993,98.74 ; 217.485,98.74 217.485,99.248 ; 217.485,99.248 217.993,99.248 ; 217.485,99.248 217.485,99.756 ; 217.485,99.756 217.485,100.264 ; 217.485,99.756 217.993,99.756 ; 217.485,100.264 217.485,100.772 ; 217.485,100.264 217.993,100.264 ; 217.485,100.772 217.993,100.772 ; 217.485,100.772 217.485,101.28 ; 217.485,101.28 217.485,101.788 ; 217.485,101.28 217.993,101.28 ; 217.485,101.788 217.485,102.296 ; 217.485,101.788 217.993,101.788 ; 217.485,102.296 217.485,102.804 ; 217.485,102.296 217.993,102.296 ; 217.485,102.804 217.485,103.312 ; 217.485,102.804 217.993,102.804 ; 217.485,103.312 217.485,103.82 ; 217.485,103.312 217.993,103.312 ; 217.485,103.82 217.485,104.328 ; 217.485,103.82 217.993,103.82 ; 217.485,104.328 217.485,104.836 ; 217.485,104.328 217.993,104.328 ; 217.485,104.836 217.485,105.344 ; 217.485,104.836 217.993,104.836 ; 217.485,105.344 217.485,105.852 ; 217.485,105.344 217.993,105.344 ; 217.485,105.852 217.485,106.36 ; 217.485,105.852 217.993,105.852 ; 217.485,106.36 217.485,106.868 ; 217.485,106.36 217.993,106.36 ; 217.485,106.868 217.485,107.376 ; 217.485,106.868 217.993,106.868 ; 217.485,107.376 217.485,107.884 ; 217.485,107.376 217.993,107.376 ; 217.485,107.884 217.485,108.392 ; 217.485,107.884 217.993,107.884 ; 217.485,108.392 217.485,108.631 ; 217.485,108.392 217.993,108.392 ; 217.485,108.631 217.993,108.631 ; 217.993,98.645 217.993,98.74 ; 217.993,98.645 217.998,98.645 217.998,98.74 ; 217.993,98.74 217.993,99.248 ; 217.993,98.74 217.998,98.74 ; 217.993,99.248 217.993,99.756 ; 217.993,99.248 217.998,99.248 ; 217.993,99.756 217.993,100.264 ; 217.993,99.756 217.998,99.756 ; 217.993,100.264 217.993,100.772 ; 217.993,100.264 217.998,100.264 ; 217.993,100.772 217.998,100.772 ; 217.993,100.772 217.993,101.28 ; 217.993,101.28 217.993,101.788 ; 217.993,101.28 217.998,101.28 ; 217.993,101.788 217.993,102.296 ; 217.993,101.788 217.998,101.788 ; 217.993,102.296 217.993,102.804 ; 217.993,102.296 217.998,102.296 ; 217.993,102.804 217.993,103.312 ; 217.993,102.804 218.501,102.804 ; 217.993,103.312 217.993,103.82 ; 217.993,103.312 218.501,103.312 ; 217.993,103.82 217.993,104.328 ; 217.993,103.82 218.501,103.82 ; 217.993,104.328 217.993,104.836 ; 217.993,104.328 218.501,104.328 ; 217.993,104.836 217.993,105.344 ; 217.993,104.836 218.501,104.836 ; 217.993,105.344 217.993,105.852 ; 217.993,105.344 218.501,105.344 ; 217.993,105.852 217.993,106.36 ; 217.993,105.852 218.501,105.852 ; 217.993,106.36 217.993,106.868 ; 217.993,106.36 218.501,106.36 ; 217.993,106.868 217.993,107.376 ; 217.993,106.868 218.501,106.868 ; 217.993,107.376 217.993,107.884 ; 217.993,107.376 218.501,107.376 ; 217.993,107.884 217.993,108.392 ; 217.993,107.884 pad.@218.501,107.884 ; 217.993,108.392 217.993,108.631 ; 217.993,108.392 pad.@218.501,108.392 ; 217.993,108.631 218.501,108.631 ; 217.998,98.74 217.998,99.248 ; 217.998,99.756 217.998,100.264 ; 217.998,100.264 217.998,100.772 ; 217.998,100.772 217.998,101.28 ; 217.998,101.28 217.998,101.788 ; 217.998,101.788 217.998,102.296 ; 217.998,102.296 217.998,102.755 218.501,102.755 ; 218.501,102.755 218.501,102.804 ; 218.501,102.755 219.009,102.755 ; 218.501,102.804 218.501,103.312 ; 218.501,102.804 219.009,102.804 ; 218.501,103.312 218.501,103.82 ; 218.501,103.312 219.009,103.312 ; 218.501,103.82 218.501,104.328 ; 218.501,103.82 219.009,103.82 ; 218.501,104.328 218.501,104.836 ; 218.501,104.328 219.009,104.328 ; 218.501,104.836 218.501,105.344 ; 218.501,104.836 219.009,104.836 ; 218.501,105.344 218.501,105.852 ; 218.501,105.344 219.009,105.344 ; 218.501,105.852 218.501,106.36 ; 218.501,105.852 219.009,105.852 ; 218.501,106.36 218.501,106.868 ; 218.501,106.36 219.009,106.36 ; 218.501,106.868 218.501,107.376 ; 218.501,106.868 219.009,106.868 ; 218.501,107.376 pad.@218.501,107.884 ; 218.501,107.376 219.009,107.376 ; pad.@218.501,107.884 pad.@218.501,108.392 ; pad.@218.501,107.884 219.009,107.884 ; pad.@218.501,108.392 218.501,108.631 ; pad.@218.501,108.392 219.009,108.392 ; 218.501,108.631 219.009,108.631 ; 219.009,102.755 219.517,102.755 ; 219.009,102.755 219.009,102.804 ; 219.009,102.804 219.517,102.804 ; 219.009,102.804 219.009,103.312 ; 219.009,103.312 219.009,103.82 ; 219.009,103.312 219.517,103.312 ; 219.009,103.82 219.009,104.328 ; 219.009,103.82 219.517,103.82 ; 219.009,104.328 219.009,104.836 ; 219.009,104.328 pad.@219.517,104.328 ; 219.009,104.836 219.009,105.344 ; 219.009,104.836 pad.@219.517,104.836 ; 219.009,105.344 219.517,105.344 ; 219.009,105.344 219.009,105.852 ; 219.009,105.852 219.009,106.36 ; 219.009,105.852 219.517,105.852 ; 219.009,106.36 219.009,106.868 ; 219.009,106.36 219.517,106.36 ; 219.009,106.868 219.009,107.376 ; 219.009,106.868 219.517,106.868 ; 219.009,107.376 219.517,107.376 ; 219.009,107.376 219.009,107.884 ; 219.009,107.884 219.512,107.884 ; 219.009,107.884 219.009,108.392 ; 219.009,108.392 219.009,108.631 ; 219.009,108.392 219.512,108.392 ; 219.009,108.631 219.512,108.631 219.512,108.392 ; 219.512,107.884 219.512,108.392 ; 219.512,107.884 219.512,107.425 219.517,107.425 ; 219.517,102.755 219.517,102.804 ; 219.517,102.755 220.025,102.755 ; 219.517,102.804 220.025,102.804 ; 219.517,102.804 219.517,103.312 ; 219.517,103.312 219.517,103.82 ; 219.517,103.312 220.025,103.312 ; 219.517,103.82 pad.@219.517,104.328 ; 219.517,103.82 220.025,103.82 ; pad.@219.517,104.328 220.025,104.328 ; pad.@219.517,104.328 pad.@219.517,104.836 ; pad.@219.517,104.836 219.517,105.344 ; pad.@219.517,104.836 220.025,104.836 ; 219.517,105.344 220.025,105.344 ; 219.517,105.344 219.517,105.852 ; 219.517,105.852 219.517,106.36 ; 219.517,105.852 220.025,105.852 ; 219.517,106.36 219.517,106.868 ; 219.517,106.36 219.815,106.36 ; 219.517,106.868 219.517,107.376 ; 219.517,106.868 219.628,106.868 ; 219.517,107.376 219.517,107.425 ; 219.517,107.376 219.612,107.376 ; 219.517,107.425 219.612,107.425 219.612,107.376 ; 219.612,107.072 ccw(c220.964,107.072) 219.628,106.868 ; 219.612,107.072 ccw(c220.964,107.072) 219.628,106.868 ; 219.612,107.072 219.612,107.376 ; 219.628,106.868 ccw(c220.964,107.072) 219.629,106.861 ; 219.628,106.868 ccw(c220.964,107.072) 219.629,106.861 ; 219.629,106.861 ccw(c220.964,107.072) 219.815,106.36 ; 219.629,106.861 ccw(c220.964,107.072) 219.815,106.36 ; 219.815,106.36 ccw(c220.964,107.072) 219.818,106.356 ; 219.815,106.36 ccw(c220.964,107.072) 219.818,106.356 ; 219.818,106.356 ccw(c220.964,107.072) 220.008,106.116 cw(c220.964,107.072) 219.818,106.356 ; 220.025,102.755 220.025,102.804 ; 220.025,102.755 220.533,102.755 ; 220.025,102.804 220.533,102.804 ; 220.025,102.804 220.025,103.312 ; 220.025,103.312 220.025,103.82 ; 220.025,103.312 220.533,103.312 ; 220.025,103.82 220.025,104.328 ; 220.025,103.82 220.533,103.82 ; 220.025,104.328 220.533,104.328 ; 220.025,104.328 220.025,104.836 ; 220.025,104.836 220.025,105.344 ; 220.025,104.836 220.533,104.836 ; 220.025,105.344 220.533,105.344 ; 220.025,105.344 220.025,105.852 ; 220.025,105.852 220.025,106.1 ; 220.025,105.852 220.273,105.852 ; 220.025,106.1 220.273,105.852 ; 220.064,96.868 cw(c220.519,95.997) 220.533,96.98 ; 220.273,105.852 220.533,105.592 ; 220.402,97.216 cw(c219.35,98.065) 220.306,97.109 ccw(c219.35,98.065) 220.402,97.216 ; 220.402,97.216 ccw(c219.35,98.065) 220.533,97.411 ; 220.402,97.216 ccw(c219.35,98.065) 220.533,97.411 ; 220.402,97.216 220.533,97.216 ; 220.533,96.98 220.533,97.216 ; 220.533,97.216 220.915,97.216 ; 220.533,97.216 220.533,97.411 ; 220.533,97.411 ccw(c219.35,98.065) 220.543,97.43 cw(c219.35,98.065) 220.533,97.411 ; 220.533,102.755 220.533,102.804 ; 220.533,102.755 220.618,102.755 220.705,102.842 220.705,103.312 ; 220.533,102.804 220.533,103.312 ; 220.533,103.312 220.533,103.82 ; 220.533,103.312 220.705,103.312 ; 220.533,103.82 220.533,104.328 ; 220.533,103.82 220.705,103.82 ; 220.533,104.328 220.533,104.836 ; 220.533,104.328 220.705,104.328 ; 220.533,104.836 220.533,105.344 ; 220.533,104.836 220.705,104.836 ; 220.533,105.344 220.705,105.344 ; 220.533,105.344 220.533,105.592 ; 220.533,105.592 220.705,105.419 220.705,105.344 ; 220.705,103.312 220.705,103.82 ; 220.705,103.82 220.705,104.328 ; 220.705,104.328 220.705,104.836 ; 220.705,104.836 220.705,105.344 ; 220.915,97.216 ccw(c221.377,98.486) 221.041,97.177 ; 221.041,96.853 221.549,96.853 ; 221.041,96.853 221.041,97.177 ; 221.549,96.853 222.057,96.853 ; 221.549,96.853 221.549,97.131 ; 221.843,97.217 ccw(c221.377,98.486) 222.053,97.315 ccw(c221.377,98.486) 222.057,97.318 ; 221.843,97.217 221.841,97.216 222.057,97.216 ; 222.057,96.853 222.057,97.216 ; 222.057,96.853 222.565,96.853 ; 222.057,97.216 222.565,97.216 ; 222.057,97.216 222.057,97.318 ; 222.057,97.318 ccw(c221.377,98.486) 222.494,97.724 ; 222.316,107.884 222.316,108.392 ; 222.316,107.884 222.565,107.884 ; 222.316,107.884 222.316,107.632 222.565,107.382 ; 222.316,108.392 222.316,108.631 222.565,108.631 ; 222.316,108.392 222.565,108.392 ; 222.494,97.724 ccw(c221.377,98.486) 222.559,97.831 ccw(c221.377,98.486) 222.565,97.841 ; 222.494,97.724 222.565,97.724 ; 222.565,96.853 223.073,96.853 ; 222.565,96.853 222.565,97.216 ; 222.565,97.216 222.565,97.724 ; 222.565,97.216 223.073,97.216 ; 222.565,97.724 223.073,97.724 ; 222.565,97.724 222.565,97.841 ; 222.565,97.841 ccw(c221.377,98.486) 222.705,98.232 ; 222.565,107.382 222.571,107.376 ; 222.565,107.382 222.565,107.884 ; 222.565,107.884 222.565,108.392 ; 222.565,107.884 223.073,107.884 ; 222.565,108.392 222.565,108.631 ; 222.565,108.392 223.073,108.392 ; 222.565,108.631 223.073,108.631 ; 222.571,107.376 223.073,107.376 ; 222.571,107.376 222.717,107.231 223.073,107.231 ; 222.705,98.232 ccw(c221.377,98.486) 222.729,98.486 222.729,98.74 ; 222.705,98.232 223.073,98.232 ; 222.729,98.74 222.729,99.248 ; 222.729,98.74 223.073,98.74 ; 222.729,99.248 223.073,99.248 ; 222.802,99.756 222.802,100.264 ; 222.802,99.756 223.073,99.756 ; 222.802,100.264 223.073,100.264 ; 222.802,100.264 222.802,100.772 ; 222.802,100.772 223.073,100.772 ; 222.802,100.772 222.802,101.115 222.967,101.28 ; 222.967,101.28 223.073,101.28 ; 223.073,96.853 223.581,96.853 ; 223.073,96.853 223.073,97.216 ; 223.073,97.216 223.073,97.724 ; 223.073,97.216 223.581,97.216 ; 223.073,97.724 223.073,98.232 ; 223.073,97.724 223.581,97.724 ; 223.073,98.232 223.073,98.74 ; 223.073,98.232 223.581,98.232 ; 223.073,98.74 223.581,98.74 ; 223.073,98.74 223.073,99.248 ; 223.073,99.248 223.581,99.248 ; 223.073,99.248 223.073,99.756 ; 223.073,99.756 223.073,100.264 ; 223.073,99.756 223.581,99.756 ; 223.073,100.264 223.581,100.264 ; 223.073,100.264 223.073,100.772 ; 223.073,100.772 223.581,100.772 ; 223.073,100.772 223.073,101.28 ; 223.073,101.28 223.581,101.28 ; 223.073,101.28 223.073,101.39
